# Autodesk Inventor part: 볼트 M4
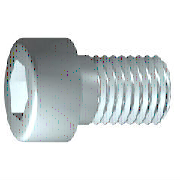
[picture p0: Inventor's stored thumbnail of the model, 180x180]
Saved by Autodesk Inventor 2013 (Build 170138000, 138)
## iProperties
IsCustomPart: 0
Created: 2012-02
Part Number: 볼트 M4
Material: 스테인리스강
Description: 6각 소켓 머리 캡 나사
Document SubType Name: Modeling
Standard: ISO 4762
Designer: mduedu
Standard Revision: Fourth edition 2004-03-01
Standards Organization: ISO
Language: ko-KR
Size Designation: M4 x 12
Categories: <MemberInstance><Categories><Category DisplayName="조임쇠" InternalName="e4da775c-781d-43d5-af7c-5136215cf5a6" Mnemonic="FSTN"><Category DisplayName="볼트" InternalN
Density: 7.75 g/cm^3
Mass: 2.20337 g
Surface Area: 3.30853 cm^2
Volume: 0.284306 cm^3
Author: mduedu
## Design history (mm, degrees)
sketch "스케치1"
  geometry: L1 (-1, 0)-(12, 0); L2 (12, 0)-(12, 2); L3 (12, 2)-(1.75, 2); L4 (1.75, 2)-(1.32, 2); L5 (1.32, 2)-(0, 2); L6 (0, 2)-(0, 3.5); L7 (0, 3.5)-(-4, 3.5); L8 (-4, 3.5)-(-4, 1.732); L9 (-4, 1.732)-(-2, 1.732); L10 (-2, 1.732)-(-1, 0); L11 (-7.2, 0)-(15.2, 0) reference; L12 (0, -0.7)-(0, 4.2) reference; L13 (1.75, 2)-(0, 2)
  constraints: 22 end point, 6 parallel, 2 collinear, 2 perpendicular, 1 horizontal, 1 point on line
  dimensions: "d1" = 10.25 distance from line of L3.end L2 (= GEL); "d2" = 0.42952 distance of L4.end L3.end (computed from GAL); "d3" = 4 distance between parallel lines of L8 L6 (= KOH); "d4" = 2 distance of L8.end L9.end (= INTI); "d5" = 60 deg angle of L10 L1; "d6" = 4 diameter of L3 L1 (= GD); "d7" = 4 diameter of L5 L1 (= BDM); "d8" = 3.4641 diameter of L9 L1 (= 1.1547 x SW); "d9" = 7 diameter of L7 L1 (= KOD); "d26" = 12 distance between parallel lines of L12 L2 (= NLG)
revolve "본체" sketch "스케치1" stored, may be unused: angle "d10" = 90 deg
sketch "스케치2"
  geometry: L1 (0, -4.9)-(0, 4.9) reference; L2 (-4.9, 0)-(4.9, 0) reference; L3 (1.732, 0)-(0.866, -1.5); L4 (0.866, -1.5)-(-0.866, -1.5); L5 (-0.866, -1.5)-(-1.732, 0); L6 (-1.732, 0)-(-0.866, 1.5); L7 (-0.866, 1.5)-(0.866, 1.5); L8 (0.866, 1.5)-(1.732, 0); 2 further points
  constraints: 12 end point, 1 coincident, 1 horizontal alignment, 1 point on line, 12 other
extrude "슬롯" join sketch "스케치2" stored distance "d11" = 10; taper "d12" = 0 deg
workplane "Work Plane1"
fillet "Fillet2" dims "d30" = 0.1 (= R)
body "Solid1"
fillet "모깎기1" dims "d17" = 0.4 (= RR)
feature "스레드" dims "d13" = 10.25 (= GEL), "d14" = 0
chamfer "모따기1" distance "d15" = 0.42941 (= -0.5 x SPD + 0.5 x GD); stored, may be unused: second distance "d16" = 0.42941 (= GUL), angle "d27" = 45 deg
other parameters: "GD" = 4 [user parameter; used in 2 equation terms], "NLG" = 12 [user parameter; used in 1 equation term], "GEL" = 10.25 [user parameter; used in 2 equation terms], "KOD" = 7 [user parameter; used in 1 equation term], "KOH" = 4 [user parameter; used in 1 equation term], "INTI" = 2 [user parameter; used in 1 equation term], "GAL" = 0.42941 (= 0.61345 x PTC) [user parameter; used in 1 equation term], "GUL" = 0.42941 (= 0.61345 x PTC) [user parameter; used in 1 equation term], "BDM" = 4 (= NND) [user parameter; used in 1 equation term], "SW" = 3 [user parameter; used in 2 equation terms], "RR" = 0.4 [user parameter; used in 1 equation term], "SPD" = 3.14117 (= NND - 1.2269 x PTC) [user parameter; used in 1 equation term], "d19" = 0, "d28" = 0, "d29" = 0, "R" = 0.1 [user parameter; used in 1 equation term], "TOA" = 30 deg [user parameter], "GD1" = 3.14117 (= THREADDIA - 1.2269 x PTC) [user parameter], "THREADDIA" = 4 [user parameter; used in 1 equation term], "FAWI" = 45 deg [user parameter], "TPU" = 14.28571 (computed from PTC) [user parameter], "PTC" = 0.7 [user parameter; used in 5 equation terms], "NND" = 4 [user parameter; used in 2 equation terms], "E0" = 3.465 (= 1.155 x SW) [user parameter]
